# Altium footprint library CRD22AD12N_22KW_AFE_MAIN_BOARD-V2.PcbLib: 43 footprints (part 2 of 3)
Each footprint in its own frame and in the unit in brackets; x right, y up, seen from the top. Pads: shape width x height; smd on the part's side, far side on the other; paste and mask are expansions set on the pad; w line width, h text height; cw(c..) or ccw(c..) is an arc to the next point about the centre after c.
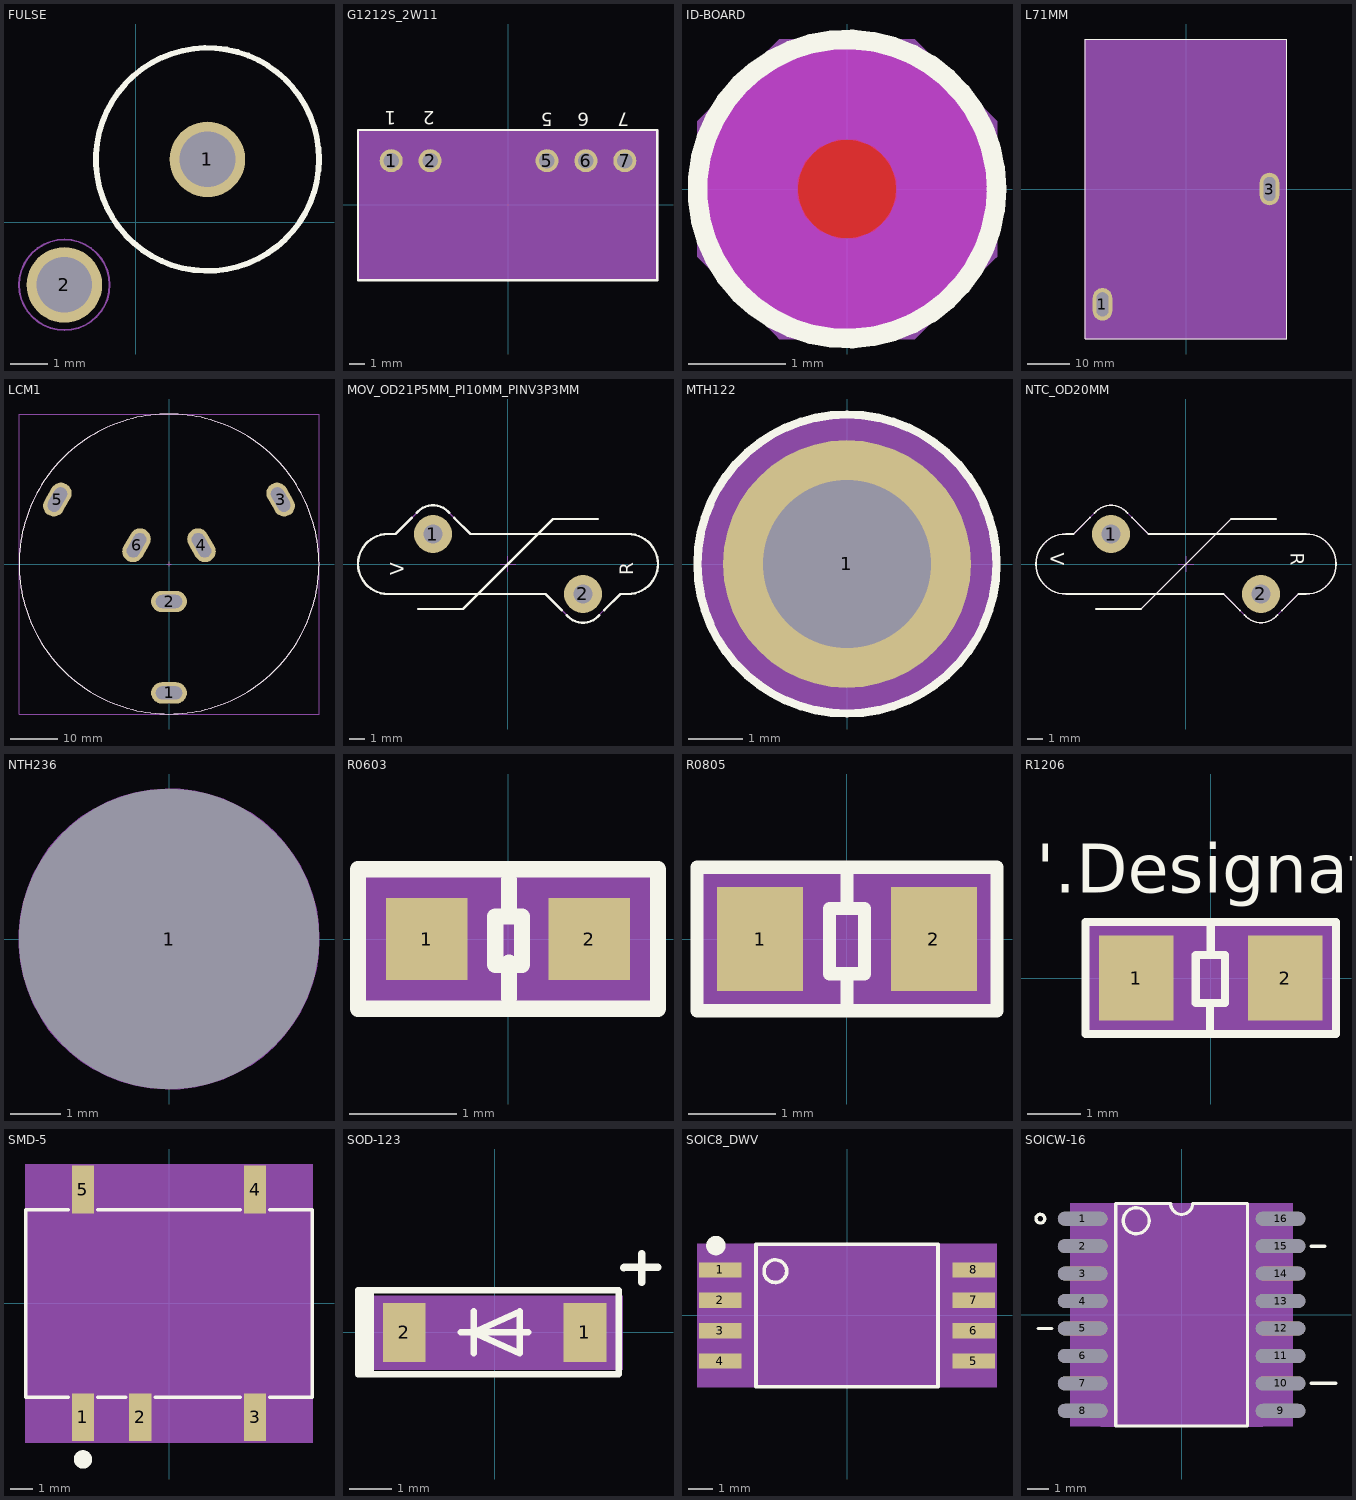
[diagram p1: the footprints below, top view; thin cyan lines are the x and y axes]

## FULSE [mil] "FULSE"
pads (2):
  round 80 hole 59: 1(75.78,66.44) 2(-75.78,-66.44)
Top Overlay:
  circle w6: c75.78,66.44 r118.11
  text ".Designator" at 105,236.67 h35
Top Component Center:
  lines w3: -95.78,-66.44 -55.78,-66.44 ; -75.78,-86.44 -75.78,-46.44
Top Assembly:
  circle w2: c75.78,66.44 r118.11
  circle w2: c-75.78,-66.44 r47.99
  text "HAMP" at -26.18,-82.44 h31
  text "#TOL" at -26.18,-82.44 h31
  text "25A" at -38.59,-82.44 h31
Mechanical 24:
  text "1" at 79.78,66.44 h10
  text "2" at -71.78,-66.44 h10
3D body: height 1000, standoff 0, extent -123.78,-114.43 -27.79,-18.44
3D body: height 1000, standoff 0, extent -101.07,-91.72 100.8,91.71
3D body: height 1000, standoff 0, extent -42.33,-51.67 193.9,184.54

## G1212S_2W11 [mil] "G1212S_2W11"
pads (5):
  round 59 hole 40: 1(-300.55,113.53) 2(-200.55,113.53) 5(99.45,113.53) 6(199.45,113.53) 7(299.45,113.53)
Top Overlay:
  lines w6: -385.7,-193.5 382.8,-193.5 382.8,192.3 -384.4,192.3 -385.7,192.3 -385.7,-193.5
  text ".Designator" at 28.7,258.27 h35
  text "1" at -287.57,240.26 h35
  text "2" at -189.15,240.26 h35
  text "5" at 114,236.32 h35
  text "6" at 208.49,236.32 h35
  text "7" at 310.85,236.32 h35
Top Courtyard:
  dashed: -384.65,-192.85 384.65,-192.85 384.65,192.85 -384.65,192.85
Top 3D Body:
  region: -384.65,-192.85 384.65,-192.85 384.65,192.85 -384.65,192.85
Top Component Center:
  lines w3: -20.55,30.85 19.45,30.85 ; -0.55,10.85 -0.55,50.85
Top Assembly:
  lines w2: -383.65,-191.85 383.65,-191.85 383.65,191.85 -383.65,191.85 -383.65,-191.85
  text "HAMP" at 49.05,14.85 h31
  text "#TOL" at 49.05,14.85 h31
  text "R15P21503D" at 123.45,14.85 h31
Mechanical 24:
  text "5" at 103.45,113.53 h10
  text "7" at 303.45,113.53 h10
  text "2" at -196.55,113.53 h10
  text "6" at 203.45,113.53 h10
  text "1" at -296.55,113.53 h10
3D body: height 150, standoff 0, extent -384.65,-192.85 384.65,192.85

## ID-BOARD [mil] "ID-BOARD"
Top Layer:
  region: 0,20 -3.98,20 -11.33,16.96 -16.96,11.33 -20,3.98 -20,0 -20,-3.98 -16.96,-11.33 -11.33,-16.96 -3.98,-20 0,-20 3.98,-20 11.33,-16.96 16.96,-11.33 20,-3.98 20,0 20,3.98 16.96,11.33 11.33,16.96 3.98,20
Top Layer keep-out:
  circle w40: c0,0 r40
Bottom Layer:
  region: 0,20 3.98,20 11.33,16.96 16.96,11.33 20,3.98 20,0 20,-3.98 16.96,-11.33 11.33,-16.96 3.98,-20 0,-20 -3.98,-20 -11.33,-16.96 -16.96,-11.33 -20,-3.98 -20,0 -20,3.98 -16.96,11.33 -11.33,16.96 -3.98,20
Top Overlay:
  circle w8: c0,0 r60.83
Bottom Overlay:
  circle w8: c0,0 r60.83
Top Solder:
  region: -60,0 -60,5.91 -57.69,17.5 -53.17,28.42 -46.6,38.25 -38.25,46.6 -28.42,53.17 -17.5,57.69 -5.91,60 0,60 5.91,60 17.5,57.69 28.42,53.17 38.25,46.6 46.6,38.25 53.17,28.42 57.69,17.5 60,5.91 60,0 60,-5.91 57.69,-17.5 53.17,-28.42 46.6,-38.25 38.25,-46.6 28.42,-53.17 17.5,-57.69 5.91,-60 0,-60 -5.91,-60 -17.5,-57.69 -28.42,-53.17 -38.25,-46.6 -46.6,-38.25 -53.17,-28.42 -57.69,-17.5 -60,-5.91
Bottom Solder:
  region: -60,0 -60,5.91 -57.69,17.5 -53.17,28.42 -46.6,38.25 -38.25,46.6 -28.42,53.17 -17.5,57.69 -5.91,60 0,60 5.91,60 17.5,57.69 28.42,53.17 38.25,46.6 46.6,38.25 53.17,28.42 57.69,17.5 60,5.91 60,0 60,-5.91 57.69,-17.5 53.17,-28.42 46.6,-38.25 38.25,-46.6 28.42,-53.17 17.5,-57.69 5.91,-60 0,-60 -5.91,-60 -17.5,-57.69 -28.42,-53.17 -38.25,-46.6 -46.6,-38.25 -53.17,-28.42 -57.69,-17.5 -60,-5.91
Bottom 3D Body:
  region: 61,27.5 61,-27.5 59.9,-28.6 27.5,-61 -27.5,-61 -28.85,-59.65 -61,-27.5 -61,27.5 -60.95,27.55 -27.5,61 27.5,61
Top Component Center:
  lines w3: -20,0 20,0 -20,0 ; 0,-20 0,20 0,-20
3D body: height 150, standoff 0, extent -61,-61 61,61

## L71MM [mil] "L71MM"
pads (2):
  oval 180x300 / inner oval 122x232 / far side oval 180x300 hole 110 slot 220 at 90 deg: 1(-767.72,-1060) 3(767.72,0)
Top Overlay:
  lines w6: -925.2,-1377.95 925.2,-1377.95 925.2,1377.95 -925.2,1377.95 -925.2,-1377.95
Top Courtyard:
  dashed: -926.18,-1378.94 926.18,-1378.94 926.18,1378.94 -926.18,1378.94
Top Component Center:
  lines w3: -20,0 20,0 ; 0,-20 0,20
Top Assembly:
  lines w2: -925.2,-1377.95 925.2,-1377.95 925.2,1377.95 -925.2,1377.95 -925.2,-1377.95
  text "HAMP" at 0,33.6 h31
  text "#TOL" at 0,33.6 h31
  text "8u" at 0,8.8 h31
  text ".Designator" at 0,8 h35
Mechanical 24:
  text "3" at 767.72,10 h25
  text "1" at -767.72,-1050 h25
3D body: height 150, standoff 0, extent -900,-1350 900,1350

## LCM1 [mil] "LCM1"
pads (6):
  oval 300x180 / inner oval 232x122 / far side oval 300x180 hole 110 slot 220 at 0 deg: 1(0,-1082.68) 2(0,-314.96)
  oval 180x300 / inner oval 122x232 / far side oval 180x300 hole 220 slot 110 at 30 deg rot 30: 3(937.63,541.34) 4(272.76,157.48)
  oval 300x180 / inner oval 232x122 / far side oval 300x180 hole 110 slot 220 at 60 deg rot 60: 5(-937.63,541.34) 6(-272.76,157.48)
Top Overlay:
  circle w8: c0,0 r1259.84
  text ".Designator" at -65,-1386.67 h35
Top Courtyard:
  lines w1: -1259.84,-1259.84 -1259.84,1259.84 1259.84,1259.84 1259.84,-1259.84 -1259.84,-1259.84
Top Component Center:
  lines w3: -20,0 20,0 ; 0,-20 0,20
Top Assembly:
  circle w2: c0,0 r1259.84
Mechanical 24:
  text "5" at -947.63,541.34 h25
  text "3" at 927.63,541.34 h25
  text "2" at -10,-314.96 h25
  text "6" at -282.76,157.48 h25
  text "4" at 262.76,157.48 h25
  text "1" at -10,-1082.68 h25
3D body: height 50, standoff 0, extent -1260,-1259.65 1260,1259.65

## MOV_OD21P5MM_PI10MM_PINV3P3MM [mil] "MOV_OD21P5MM_PI10MM_PINV3P3MM"
pads (2):
  round 100 hole 51: 1(-196.85,78.74) 2(196.85,-78.74)
Top Overlay:
  lines w6: -295.28,78.74 -295.27,78.74 ; -252.95,121.06 -295.27,78.74 ; -239.17,134.84 -236.21,137.8 cw(c-196.85,98.43) -157.49,137.8 -154.53,134.84 ; -236.22,-118.11 -118.11,-118.11 118.11,118.11 236.22,118.11 ; -140.75,121.06 -98.43,78.74 314.96,78.74 cw(c314.96,0) 314.96,-78.74 295.27,-78.74 252.95,-121.06 ; 140.75,-121.06 98.43,-78.74 -314.96,-78.74 cw(c-314.96,0) -314.96,78.74 -295.27,78.74 ; 154.53,-134.84 157.49,-137.8 ccw(c196.85,-98.43) 236.21,-137.8 239.17,-134.84
  text "R" at 328.29,-30 h35
  text "V" at -273.33,-30 h35
  text ".Designator" at 60,-138.33 h35
Top Courtyard:
  lines w2: -295.23,78.74 -314.92,78.74 ccw(c-314.92,0) -314.92,-78.74 98.47,-78.74 157.53,-137.8 ccw(c196.89,-98.43) 236.25,-137.8 295.31,-78.74 315,-78.74 ccw(c315,0) 315,78.74 -98.39,78.74 -157.45,137.8 ccw(c-196.81,98.43) -236.17,137.8 -295.23,78.74 ; -295.24,78.74 -295.23,78.74
Top Component Center:
  lines w3: -20,0 20,0 ; 0,-20 0,20
Top Assembly:
  lines w2: -295.28,78.74 -295.27,78.74 ; -236.22,-118.11 -118.11,-118.11 118.11,118.11 236.22,118.11 ; -295.27,78.74 -314.96,78.74 ccw(c-314.96,0) -314.96,-78.74 98.43,-78.74 157.49,-137.8 ccw(c196.85,-98.43) 236.21,-137.8 295.27,-78.74 314.96,-78.74 ccw(c314.96,0) 314.96,78.74 -98.43,78.74 -157.49,137.8 ccw(c-196.85,98.43) -236.21,137.8 -295.27,78.74
  text "S20K625" at 0,-102.8 h31
  text "#TOL" at 0,-65.6 h31
  text "HAMP" at 0,-65.6 h31
Mechanical 24:
  text "2" at 196.85,-82.74 h10
  text "1" at -196.85,74.74 h10
3D body: height 20, standoff 0, extent -394.71,-155.12 394.71,155.12

## MTH122 [mil] "MTH122"
pads (1):
  round 180 hole 122: 1(0,0)
Top Overlay:
  circle w6: c0,0 r108.63
Top 3D Body:
  region: 0,-108.96 17.05,-107.62 33.67,-103.63 49.47,-97.09 64.05,-88.15 77.05,-77.05 88.15,-64.05 97.09,-49.47 103.63,-33.67 107.62,-17.05 108.96,0 107.62,17.05 103.63,33.67 97.09,49.47 94.11,54.33 88.15,64.05 77.05,77.05 64.05,88.15 49.47,97.09 33.67,103.63 17.05,107.62 0,108.96 -17.05,107.62 -33.67,103.63 -49.47,97.09 -64.05,88.15 -77.05,77.05 -88.15,64.05 -94.11,54.33 -97.09,49.47 -103.63,33.67 -107.62,17.05 -108.96,0 -107.62,-17.05 -103.63,-33.67 -97.09,-49.47 -88.15,-64.05 -77.05,-77.05 -64.05,-88.15 -49.47,-97.09 -33.67,-103.63 -17.05,-107.62
Top Component Center:
  lines w3: -20,0 20,0 ; 0,-20 0,20
Top Assembly:
  circle w2: c0,0 r108.63
3D body: height 150, standoff 0, extent -108.96,-108.96 108.96,108.96

## NTC_OD20MM [mil] "NTC_OD20MM"
pads (2):
  round 100 hole 51: 1(-196.85,78.74) 2(196.85,-78.74)
Top Overlay:
  lines w4: -295.28,78.74 -295.27,78.74 ; -251.95,122.06 -295.27,78.74 ; -240.17,133.84 -236.21,137.8 cw(c-196.85,98.43) -157.49,137.8 -153.53,133.84 ; -236.22,-118.11 -118.11,-118.11 118.11,118.11 236.22,118.11 ; -141.75,122.06 -98.43,78.74 314.96,78.74 cw(c314.96,0) 314.96,-78.74 295.27,-78.74 251.95,-122.06 ; 141.75,-122.06 98.43,-78.74 -314.96,-78.74 cw(c-314.96,0) -314.96,78.74 -295.27,78.74 ; 153.53,-133.84 157.49,-137.8 ccw(c196.85,-98.43) 236.21,-137.8 240.17,-133.84
  text ".Designator" at -50,95 h35
  text "V" at -354.96,30 h35
  text "R" at 274.96,30 h35
Top Component Center:
  lines w3: -20,0 20,0 ; 0,-20 0,20
Top Assembly:
  lines w2: -295.28,78.74 -295.27,78.74 ; -236.22,-118.11 -118.11,-118.11 118.11,118.11 236.22,118.11 ; -295.27,78.74 -236.21,137.8 cw(c-196.85,98.43) -157.49,137.8 -98.43,78.74 314.96,78.74 cw(c314.96,0) 314.96,-78.74 295.27,-78.74 236.21,-137.8 cw(c196.85,-98.43) 157.49,-137.8 98.43,-78.74 -314.96,-78.74 cw(c-314.96,0) -314.96,78.74 -295.27,78.74
  text "HAMP" at 0,33.6 h31
  text "#TOL" at 0,33.6 h31
  text "NTC" at 0,21.2 h31
Mechanical 24:
  text "1" at -196.85,82.74 h10
  text "2" at 196.85,-74.74 h10
3D body: height 20, standoff 0, extent -393.7,-154.1 393.7,154.1

## NTH236 [mil] "NTH236"
pads (1):
  round 236 hole 236 unplated: 1(0,0)
Top Assembly:
  circle w1: c0,0 r118.11

## R0603 [mil] "R0603"
pads (2):
  rect 30x30 smd: 1(-29.92,0) 2(29.92,0)
Top Overlay:
  lines w6: 0.39,-21.65 0.39,-8.66 ; 0.39,9.45 0.39,21.65 ; -55.12,-25.59 55.12,-25.59 55.12,25.59 -55.12,25.59 -55.12,-25.59 ; -4.72,-9.45 -4.72,8.27 5.12,8.27 5.12,-9.45 -4.72,-9.45
  text ".Designator" at 60,86.67 h35
Top 3D Body:
  region: -31.5,-15.75 -31.5,15.75 31.5,15.75 31.5,-15.75
Top Component Center:
  region: -55,25 55,25 55,-25 -55,-25
  lines w3: -20,0 20,0 ; 0,-20 0,20
Top Assembly:
  lines w2: -55,-25 55,-25 55,25 -55,25 -55,-25
  text "10k" at -37.2,-16 h31
  text "#TOL" at -49.6,-16 h31
  text "HAMP" at -49.6,-16 h31
Mechanical 24:
  text "1" at -33.92,0 h10
  text "2" at 25.92,0 h10
3D body: height 50, standoff 0, extent -31.5,-15.75 31.5,15.75

## R0805 [mil] "R0805"
pads (2):
  rect 39x47 smd: 1(-39.37,0) 2(39.37,0)
Top Overlay:
  lines w6: 0,-31.5 0,-17.72 ; 0,15.75 0,31.5 ; -67.91,-32.48 -67.91,32.48 67.91,32.48 67.91,-32.48 -67.91,-32.48 ; -7.87,-15.75 7.87,-15.75 7.87,13.78 -7.87,13.78 -7.87,-15.75
  text ".Designator" at 80,-21.67 h35
Top Courtyard:
  region: -65,-30 -65,30 65,30 65,-30
Top Component Center:
  lines w3: -20,0 20,0 ; 0,-20 0,20
Top Assembly:
  lines w2: -65,-30 -65,30 65,30 65,-30 -65,-30
  text "HAMP" at -55,-15.6 h31
  text "#TOL" at -55,-15.6 h31
  text "1R" at -55,9.2 h31
Mechanical 24:
  text "2" at 39.37,-4 h10
  text "1" at -39.37,-4 h10
3D body: height 50, standoff 0, extent -39.37,-24.61 39.37,24.61

## R1206 [mil] "R1206"
pads (2):
  rect 55x63 smd: 1(-55.12,0) 2(55.12,0)
Top Overlay:
  lines w6: -0.39,-41.34 -0.39,-18.5 ; 0,18.9 0,40.94 ; -92.52,-41.34 -92.52,41.34 92.52,41.34 92.52,-41.34 -92.52,-41.34 ; -11.02,-18.5 10.63,-18.5 10.63,16.93 -11.02,16.93 -11.02,-18.5
  text "'.Designator'" at -129,63 h36
Top Courtyard:
  region: -90,-40 -90,40 90,40 90,-40
Top Component Center:
  lines w3: -20,0 20,0 ; 0,-20 0,20
Top Assembly:
  lines w2: -90,-40 -90,40 90,40 90,-40 -90,-40
Mechanical 24:
  text "1" at -55.12,4 h10
  text "2" at 55.12,4 h10
3D body: height 50, standoff 0, extent -61.02,-31.5 61.02,31.5

## SMD-5 [mil] "SMD-5"
pads (5):
  rect 39x83 smd: 1(-150,-198.5) 2(-50,-198.5) 3(150,-198.5) 4(150,198.5) 5(-150,198.5)
Top Overlay:
  circle w16: c-150,-272 r8
  lines w5.91: -175.56,-163.5 -250,-163.5 -250,163.5 -175.56,163.5 ; -124.44,-163.5 -75.56,-163.5 ; -124.44,163.5 124.44,163.5 ; -24.45,-163.5 124.44,-163.5 ; 175.56,-163.5 250,-163.5 250,163.5 175.56,163.5
  text ".Designator" at -311.67,20 h35
Top Courtyard:
  region: -251,-243 251,-243 251,243 -251,243
Top Component Center:
  lines w3: -20,0 20,0 ; 0,-20 0,20
Top Assembly:
  circle w16: c-207.35,-129.5 r8
  lines w2: -250,-163.5 -250,163.5 250,163.5 250,-163.5 -250,-163.5
  text "PS_B0505XT" at 0,108 h31
  text "#TOL" at 0,33.6 h31
  text "HAMP" at 0,33.6 h31
Mechanical 24:
  text "2" at -50,-188.5 h25
  text "3" at 150,-188.5 h25
  text "1" at -150,-188.5 h25
  text "4" at 150,208.5 h25
  text "5" at -150,208.5 h25
3D body: height 150, standoff 0, extent -251,-165 251,165

## SOD-123 [mm] "SOD-123"
pads (2):
  rect 1.02x1.4 smd: 1(2.15,0) 2(-2.15,0)
Top Overlay:
  lines w0.152: -3.1,-1 -3.1,1 ; -2.95,-1 -2.95,1 ; -0.8,0 0.8,0 ; -0.5,-0.5 -0.5,0.5 ; -3.25,-1 2.95,-1 2.95,1 -3.25,1 -3.25,-1 ; -0.5,0 0.6,-0.5 0.6,0.5 -0.5,0
  lines w0.178: 3.071,1.542 3.081,1.552 3.889,1.552 ; 3.504,1.198 3.504,1.876
  text ".Designator" at 1.143,-1.27 h0.89
Top 3D Body:
  region: 3.05,0.875 3.05,-0.875 -3.05,-0.875 -3.05,0.875
Top Component Center:
  lines w0.076: -0.508,0 0.508,0 ; 0,-0.508 0,0.508
Top Assembly:
  lines w0.025: -3.05,-0.875 3.05,-0.875 3.05,0.875 -3.05,0.875 -3.05,-0.875
  text "1N4148W" at -2.205,0.406 h0.79
  text "#TOL" at -1.26,0.406 h0.79
  text "HAMP" at -1.26,0.406 h0.79
Mechanical 24:
  text "2" at -2.252,0 h0.25
  text "1" at 2.048,0 h0.25
3D body: height 3.81, standoff 0, extent -3.05,-0.875 3.05,0.875

## SOIC8_DWV [mil] "SOIC8_DWV"
pads (8):
  rect 70x25 smd: 1(-208.66,75) 2(-208.66,25) 3(-208.66,-25) 4(-208.66,-75) 5(208.66,-75) 6(208.66,-25) 7(208.66,25) 8(208.66,75)
Top Overlay:
  circle w5.91: c-117.81,72.83 r18.66
  circle w16: c-215.66,115 r8
  lines w5.91: -149.61,-117.13 -149.61,117.13 149.61,117.13 149.61,-117.13 -149.61,-117.13
Top Courtyard:
  dashed: -246.66,-118.11 246.66,-118.11 246.66,118.11 -246.66,118.11
Top 3D Body:
  region: -246.66,-118.11 246.66,-118.11 246.66,118.11 -246.66,118.11
Top Component Center:
  lines w3: -20,0 20,0 ; 0,-20 0,20
Top Assembly:
  circle w1.97: c-117.81,72.83 r18.66
  lines w1.97: -149.61,-117.13 -149.61,117.13 149.61,117.13 149.61,-117.13 -149.61,-117.13
  text ".Designator" at 42,-20 h35
  text "UCC5350MC" at 111.6,-16 h31
  text "#TOL" at 49.6,-16 h31
  text "HAMP" at 49.6,-16 h31
Mechanical 24:
  text "7" at 228.66,25 h25
  text "6" at 228.66,-25 h25
  text "8" at 228.66,75 h25
  text "1" at -188.66,75 h25
  text "5" at 228.66,-75 h25
  text "2" at -188.66,25 h25
  text "4" at -188.66,-75 h25
  text "3" at -188.66,-25 h25
3D body: height 150, standoff 0, extent -246.66,-118.11 246.66,118.11

## SOICW-16 [mil] "SOICW-16"
pads (16):
  oval 90x25 smd: 1(-180.24,175) 2(-180.24,125) 3(-180.24,75) 4(-180.24,25) 5(-180.24,-25) 6(-180.24,-75) 7(-180.24,-125) 8(-180.24,-175) 9(180.24,-175) 10(180.24,-125) 11(180.24,-75) 12(180.24,-25) 13(180.24,25) 14(180.24,75) 15(180.24,125) 16(180.24,175)
Top Overlay:
  circle w5.98: c-257.24,175 r7.99
  circle w5.98: c-82.68,171.26 r23.7
  lines w5.91: -120.08,-202.76 -120.08,202.76 -20,202.76 ccw(c0,202.76) 20,202.76 120.08,202.76 120.08,-202.76 -120.08,-202.76
  lines w5.98: -261.22,-25 -236.22,-25 ; 236.22,-125 281.22,-125 ; 236.22,125 261.22,125
  text ".Designator" at 55,-238.33 h35
Top 3D Body:
  region: -202.76,-202.76 -202.76,202.76 202.76,202.76 202.76,-202.76
Top Component Center:
  lines w2.99: -20,0 20,0 ; 0,-20 0,20
Top Assembly:
  circle w2.01: c-82.68,171.26 r23.7
  lines w1.97: -147.64,-202.76 -147.64,202.76 -20,202.76 ccw(c0,202.76) 20,202.76 147.64,202.76 147.64,-202.76 -147.64,-202.76
  text "ACS733" at 0,58.42 h31
  text "#TOL" at 0,33.62 h31
  text "HAMP" at 0,33.62 h31
Mechanical 24:
  text "9" at 180.24,-165 h25
  text "10" at 180.24,-105 h25
  text "11" at 180.24,-55 h25
  text "1" at -180.24,185 h25
  text "2" at -180.24,135 h25
  text "3" at -180.24,85 h25
  text "4" at -180.24,35 h25
  text "14" at 180.24,95 h25
  text "16" at 180.24,195 h25
  text "15" at 180.24,145 h25
  text "8" at -180.24,-165 h25
  text "5" at -180.24,-15 h25
  text "6" at -180.24,-65 h25
  text "7" at -180.24,-115 h25
  text "12" at 180.24,-5 h25
  text "13" at 180.24,45 h25
3D body: height 150, standoff 0, extent -202.76,-202.76 202.76,202.76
